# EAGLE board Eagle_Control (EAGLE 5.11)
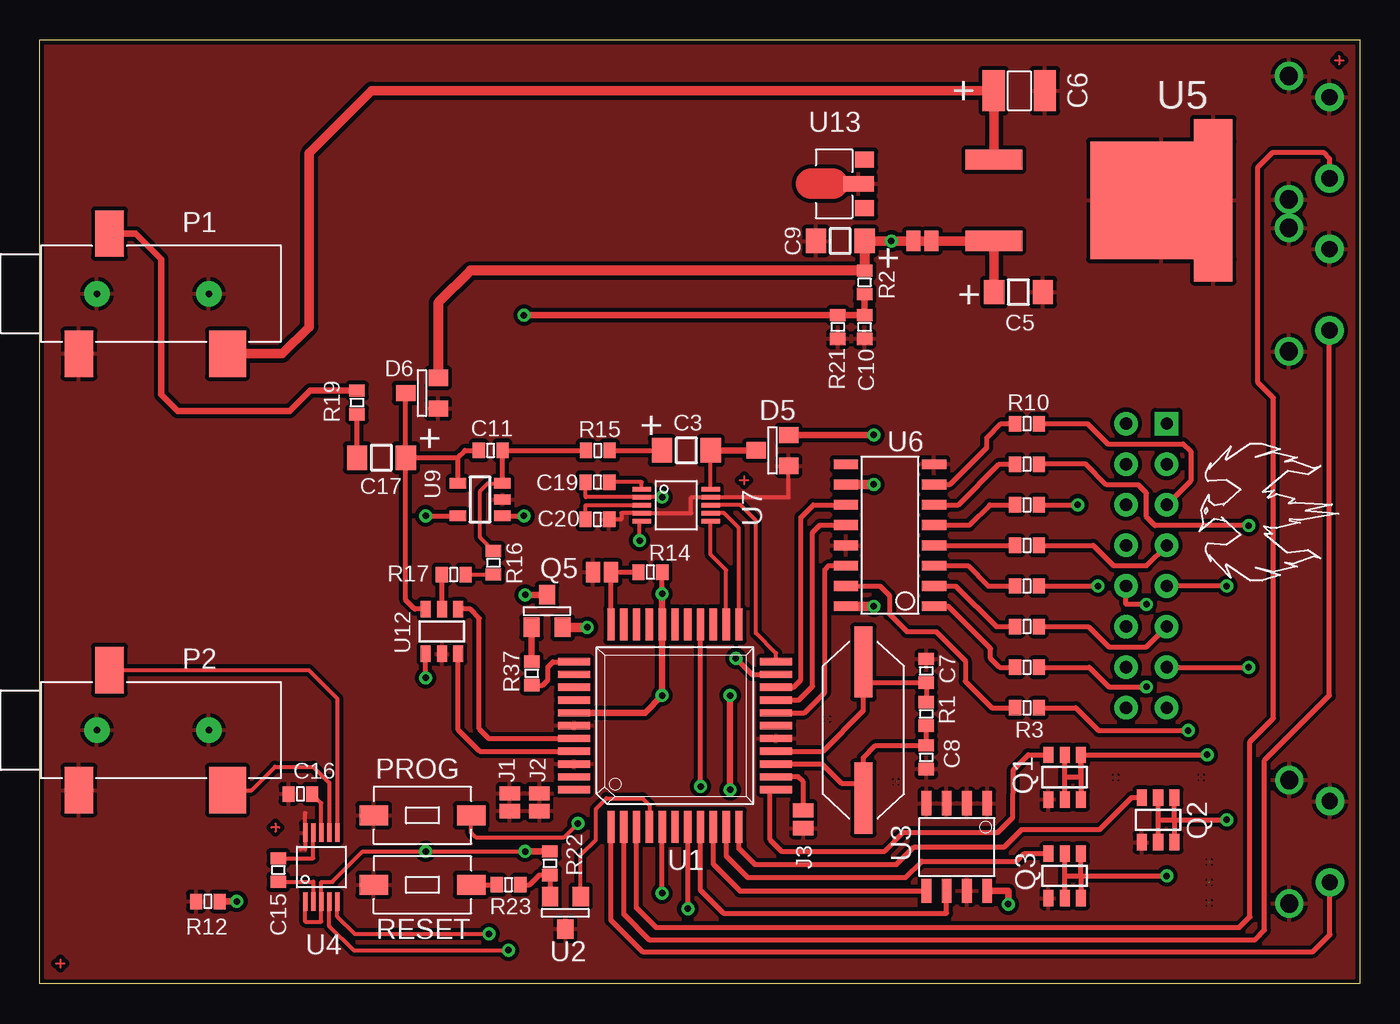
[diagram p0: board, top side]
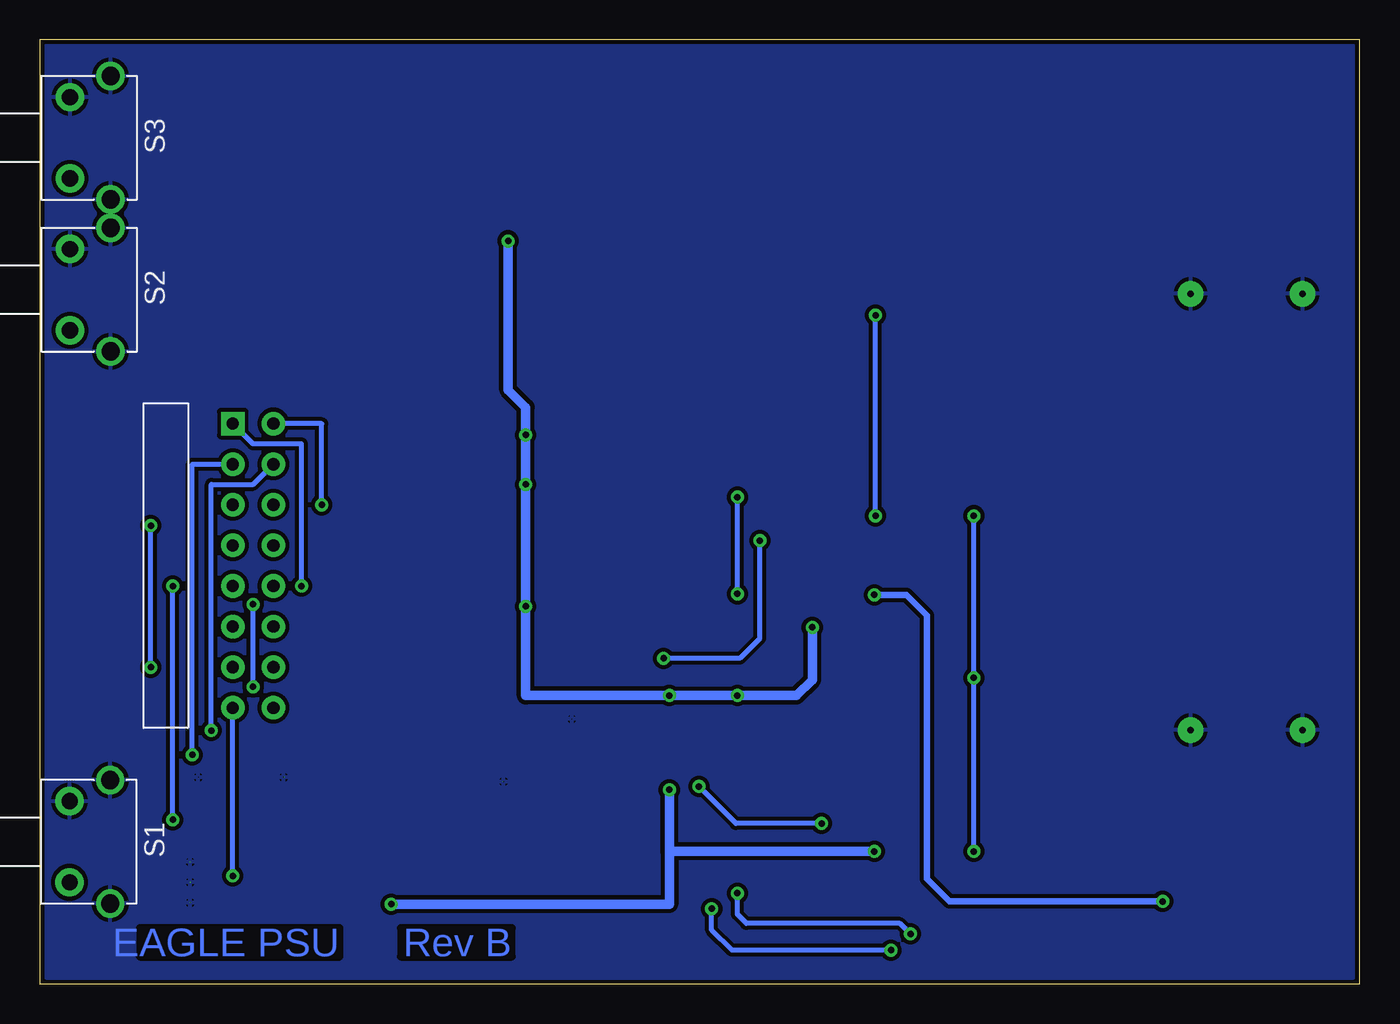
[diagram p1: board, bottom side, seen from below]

Size 82.55 x 59.05 mm. Coordinates in mm from the lower left corner, seen from the top.
Outline: 0,0 0,59.05 82.55,59.05 82.55,0 0,0
Copper layers (1*16): Top 0.035mm / dielectric 1.5mm / Bottom 0.035mm
Design rules "default *": minimum track width 10mil, minimum drill 1mil, track to track 8mil, track to pad 8mil, pad to pad 8mil, via to via 8mil, smd to smd 8mil, copper to edge 0mil, drill to drill 8mil, minimum pad ring 0mil, minimum via ring 0mil, stop-mask expansion 4mil, vias tented up to drill 20mil, thermal gap 10mil

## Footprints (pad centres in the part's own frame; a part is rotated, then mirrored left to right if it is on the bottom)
C1206 = smd 1.524 x 1.27: P$1 0,1.524; P$2 0,-1.524
1210 = smd 1.397 x 2.591: 1 -1.6,0; 2 1.6,0
C0603 = smd 0.762 x 0.965: P$1 -0.737,0; P$2 0.737,0
SOT23 = smd 1.016 x 1.219: 1 -0.94,1.016; 2 0.991,1.016; 3 0.025,-1.016
SMJUMP-S = smd 0.889 x 1.27: P$1 0.559,0; P$2 -0.559,0
DIP16_RA = drill 0.762 pad 1.473 square: P$1 -8.89,-1.27 | drill 0.762 pad 1.473 round: P$2 -6.35,-1.27; P$3 -3.81,-1.27; P$4 -1.27,-1.27; P$5 1.27,-1.27; P$6 3.81,-1.27; P$7 6.35,-1.27; P$8 8.89,-1.27; P$9 8.89,1.27; P$10 6.35,1.27; P$11 3.81,1.27; P$12 1.27,1.27; P$13 -1.27,1.27; P$14 -3.81,1.27; P$15 -6.35,1.27; P$16 -8.89,1.27
CSM7 = smd 4.445 x 1.143: P$1 0,0; P$2 8.509,0
GNDVIA = drill 0.025 pad 0.046 round: P$1 0,0
3.5MMST_RA_SMT-3 = smd 1.803 x 2.896: P$1 5.131,3.759; P$2 3.226,-3.759 | smd 2.311 x 2.896: P$3 -4.166,3.759 | drill 0.406 pad 1.587 round: P$5 -2.997,0; P$6 4.013,0
SPST3X6 = smd 1.778 x 1.27: P$1 3.048,0; P$2 -3.048,0
SOT6 = smd 1.016 x 0.635: P$1 1.397,-1.016; P$2 1.397,0; P$3 -1.397,0; P$4 -1.397,-1.016; P$5 -1.397,1.016; P$6 1.397,1.016
C603_90 = smd 0.965 x 0.762: P$1 0,0.737; P$2 0,-0.737
TACTRA = drill 1.143 pad 1.778 round: P$1 1.346,-3.861; P$2 1.346,3.861 | drill 1.016 pad 1.778 round: P$3 -1.194,2.54; P$4 -1.194,-2.54
QFP-44 = smd 0.457 x 2.007: 1 -4,-6.325; 2 -3.2,-6.325; 3 -2.4,-6.325; 4 -1.6,-6.325; 5 -0.8,-6.325; 6 0,-6.325; 7 0.8,-6.325; 8 1.6,-6.325; 9 2.4,-6.325; 10 3.2,-6.325; 11 4,-6.325; 23 4,6.325; 24 3.2,6.325; 25 2.4,6.325; 26 1.6,6.325; 27 0.8,6.325; 28 0,6.325; 29 -0.8,6.325; 30 -1.6,6.325; 31 -2.4,6.325; 32 -3.2,6.325; 33 -4,6.325 | smd 2.007 x 0.457: 12 6.325,-4; 13 6.325,-3.2; 14 6.325,-2.4; 15 6.325,-1.6; 16 6.325,-0.8; 17 6.325,0; 18 6.325,0.8; 19 6.325,1.6; 20 6.325,2.4; 21 6.325,3.2; 22 6.325,4; 34 -6.325,4; 35 -6.325,3.2; 36 -6.325,2.4; 37 -6.325,1.6; 38 -6.325,0.8; 39 -6.325,0; 40 -6.325,-0.8; 41 -6.325,-1.6; 42 -6.325,-2.4; 43 -6.325,-3.2; 44 -6.325,-4
SO-8 = smd 0.61 x 1.524: 1 -1.27,-2.743; 2 0,-2.743; 3 1.27,-2.743; 4 2.54,-2.743; 5 2.54,2.743; 6 1.27,2.743; 7 0,2.743; 8 -1.27,2.743
10UMAX = smd 0.279 x 1.143: P$1 -1,-2.16; P$2 -0.5,-2.16; P$3 0,-2.16; P$4 0.5,-2.16; P$5 1,-2.16; P$6 1,2.16; P$7 0.5,2.16; P$8 0,2.16; P$9 -0.5,2.16; P$10 -1,2.16
TO263 = smd 7.366 x 8.89: P$1 0,0 | smd 1.27 x 3.556: P$2 -2.54,-10.477; P$3 2.54,-10.477 | smd 10.16 x 2.413: P$4 0,3.239
SO-16 = smd 0.61 x 1.524: 1 -3.81,-2.819; 2 -2.54,-2.819; 3 -1.27,-2.819; 4 0,-2.819; 5 1.27,-2.819; 6 2.54,-2.819; 7 3.81,-2.819; 8 5.08,-2.819; 9 5.08,2.692; 10 3.81,2.692; 11 2.54,2.692; 12 1.27,2.692; 13 0,2.692; 14 -1.27,2.692; 15 -2.54,2.692; 16 -3.81,2.692
SOT23-5 = smd 1.016 x 0.635: 1 -1.397,1.016; 2 -1.397,0; 3 -1.397,-1.016; 4 1.397,-1.016; 5 1.397,1.016
SOT-89 = smd 0.991 x 1.194: 1 -1.524,-1.829; 2 1.524,-1.829 | smd 0.991 x 1.905: 3 0,-1.448

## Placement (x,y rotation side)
C3  [C1206]  40.44,33.38 90 top
C5  [C1206]  61.21,43.28 90 top
C6  [1210]  61.26,55.88 0 top
C7  [C0603]  55.45,19.58 90 top
C8  [C0603]  55.45,14.17 90 top
C9  [C1206]  50.06,46.48 90 top
C10  [C0603]  51.59,41.1 90 top
C11  [C0603]  28.19,33.38 0 top
C15  [C0603]  14.91,7.12 90 top
C16  [C0603]  16.29,11.87 0 top
C17  [C1206]  21.36,32.92 90 top
C19  [C0603]  34.87,31.39 0 top
C20  [C0603]  34.87,29.06 0 top
D5  [SOT23]  45.82,33.4 270 top
D6  [SOT23]  23.9,36.98 270 top
E$1  [SMJUMP-S]  29.39,11.37 90 top
E$2  [SMJUMP-S]  55.21,46.48 0 top
E$4  [SMJUMP-S]  31.24,11.37 90 top
E$11  [PHOENIX_LOGO]  75.69,29.51 90 top
E$12  [DIP16_RA]  69.22,26.16 270 bottom
E$13  [CSM7]  51.51,11.62 90 top
E$15  [SMJUMP-S]  35.17,25.76 180 top
E$16  [GNDVIA]  73.15,7.62 0 top
E$17  [GNDVIA]  73.15,6.35 0 top
E$18  [GNDVIA]  73.15,5.08 0 top
E$19  [GNDVIA]  67.31,12.93 0 top
E$20  [GNDVIA]  72.64,12.93 0 top
E$21  [GNDVIA]  49.28,16.56 0 top
E$22  [GNDVIA]  53.54,12.65 0 top
E$23  [SMJUMP-S]  47.75,10.3 90 top
P1  [3.5MMST_RA_SMT-3]  7.57,43.18 180 top
P2  [3.5MMST_RA_SMT-3]  7.57,15.88 180 top
PROG  [SPST3X6]  23.93,10.54 180 top
Q1  [SOT6]  64.11,12.93 270 top
Q2  [SOT6]  69.95,10.26 270 top
Q3  [SOT6]  64.11,6.76 270 top
Q5  [SOT23]  31.75,23.32 180 top
R1  [C0603]  55.45,16.89 90 top
R2  [C0603]  51.59,43.89 90 top
R3  [C603_90]  61.75,17.27 90 top
R4  [C603_90]  61.75,19.81 90 top
R5  [C603_90]  61.75,22.35 90 top
R6  [C603_90]  61.75,24.89 90 top
R7  [C603_90]  61.75,27.43 90 top
R8  [C603_90]  61.75,29.97 90 top
R9  [C603_90]  61.75,32.51 90 top
R10  [C603_90]  61.75,35.05 90 top
R12  [C0603]  10.5,5.16 0 top
R14  [C0603]  38.19,25.76 180 top
R15  [C0603]  34.9,33.38 0 top
R16  [C0603]  28.37,26.34 90 top
R17  [C0603]  25.88,25.6 0 top
R19  [C0603]  19.84,36.37 270 top
R21  [C0603]  49.91,41.1 90 top
R22  [C0603]  31.9,7.54 90 top
R23  [C0603]  29.31,6.2 0 top
R37  [C0603]  30.76,19.42 90 top
RESET  [SPST3X6]  23.93,6.2 180 top
S1  [TACTRA]  79.5,8.89 0 bottom
S2  [TACTRA]  79.48,43.43 0 bottom
S3  [TACTRA]  79.48,52.93 0 bottom
U1  [QFP-44]  39.73,16.15 0 top
U2  [SOT23]  32.84,4.45 0 top
U3  [SO-8]  57.99,8.56 180 top
U4  [10UMAX]  17.6,7.3 0 top
U5  [TO263]  70.15,49.02 270 top
U6  [SO-16]  53.11,27.43 90 top
U7  [10UMAX]  39.8,29.95 270 top
U9  [SOT23-5]  27.53,30.3 180 top
U12  [SOT6]  25.15,22.05 90 top
U13  [SOT-89]  49.76,50.05 90 top

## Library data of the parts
C3 C5 C7-C11 C15-C17 C19 C20 D5 D6 E$16-E$22 Q1-Q3 Q5 R1-R10 R12 R14-R17 R19 R21-R23 R37 U2 U9 U12 = RF
C6 U13 = SMD
E$1 E$2 E$4 E$11 E$13 E$15 E$23 P1 P2 PROG RESET S1-S3 = WJC
E$12 = pinhead
U1 U3-U7 = SMD-IC

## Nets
$BIAS: C10.P$2 R2.P$1 R21.P$2 U9.1
$GND: C5.P$2 C6.2 C7.P$2 C8.P$1 C9.P$1 C10.P$1 C16.P$1 C20.P$2 D5.2 D6.2 E$1.P$1 E$1.P$2 E$4.P$1 E$4.P$2 E$15.P$1 E$16.P$1 E$17.P$1 E$18.P$1 E$19.P$1 E$20.P$1 E$21.P$1 E$22.P$1 E$23.P$2 P1.P$1 P1.P$5 P1.P$6 P2.P$1 P2.P$5 P2.P$6 PROG.P$1 Q1.P$1 Q2.P$1 Q3.P$1 R12.P$1 R21.P$1 RESET.P$1 S1.P$1 S1.P$2 S1.P$3 S2.P$1 S2.P$2 S2.P$3 S3.P$1 S3.P$2 S3.P$3 U1.16 U1.39 U1.42 U2.3 U3.1 U3.2 U3.3 U3.4 U3.7 U4.P$10 U5.P$1 U5.P$4 U6.8 U6.13 U7.P$4 U7.P$9 U9.2 U12.P$3 U13.3
$VCC: C5.P$1 C9.P$2 C19.P$1 D5.1 D6.1 E$2.P$1 E$2.P$2 Q5.1 R2.P$2 R14.P$1 R22.P$2 U1.29 U1.38 U3.8 U4.P$1 U4.P$3 U5.P$3 U6.10 U6.16 U7.P$2 U9.5 U12.P$5
S$1: U1.4 U2.2
S$2: U1.5 U4.P$5
S$4: U1.8 U3.6
S$5: U1.7 U4.P$4
S$6: U1.9 U3.5
S$7: PROG.P$2 U1.26
S$8: R4.P$1 U6.1
S$9: Q3.P$4 U1.10
S$10: Q2.P$4 U1.11
S$11: R5.P$1 U6.2
S$12: R6.P$1 U6.3
S$13: R7.P$1 U6.4
S$14: R8.P$1 U6.5
S$15: R9.P$1 U6.6
S$16: R10.P$1 U6.7
S$17: R3.P$1 U6.15
S$18: E$12.P$15 R3.P$2
S$19: E$12.P$12 R4.P$2
S$20: E$12.P$6 R5.P$2
S$21: E$12.P$1 R6.P$2
S$22: E$12.P$4 R7.P$2
S$23: E$12.P$16 R8.P$2
S$24: E$12.P$7 R9.P$2
S$25: E$12.P$3 R10.P$2
S$26: E$12.P$2 Q1.P$2 Q1.P$3 Q1.P$5 Q1.P$6
S$27: Q1.P$4 U1.12
S$28: C6.1 P1.P$3 U5.P$2
S$29: C7.P$1 E$13.P$2 R1.P$2 U1.15
S$30: S1.P$4 U1.1
S$31: E$12.P$5 Q2.P$2 Q2.P$3 Q2.P$5 Q2.P$6
S$32: E$12.P$8 Q3.P$2 Q3.P$3 Q3.P$5 Q3.P$6
S$33: S2.P$4 U1.2
S$34: C8.P$2 E$13.P$1 R1.P$1 U1.14
S$35: S3.P$4 U1.3
S$36: U1.24 U7.P$6
S$37: U1.23 U7.P$7
S$38: U1.22 U7.P$8
S$39: U1.21 U7.P$5
S$40: R37.P$1 U1.34
S$41: U1.20 U6.11
S$42: U1.19 U6.12
S$43: U1.18 U6.14
S$44: Q5.3 R12.P$2
S$45: P1.P$2 R19.P$1
S$46: P2.P$3 U4.P$7
S$49: E$15.P$2 R14.P$2 U1.33
S$50: C15.P$2 U4.P$9
S$51: C15.P$1 U4.P$2
S$52: C3.P$1 R15.P$2
S$55: C3.P$2 D5.3 U7.P$10
S$56: P2.P$2 U4.P$6
S$57: C11.P$1 C17.P$2 D6.3 U9.4 U12.P$6
S$59: R17.P$1 U12.P$2
S$60: R22.P$1 R23.P$2 U2.1
S$61: C11.P$2 R15.P$1 R16.P$2 U9.3
S$65: R23.P$1 RESET.P$2
S$72: C16.P$2 U4.P$8
S$73: C17.P$1 R19.P$2
S$75: C19.P$2 U7.P$1
S$76: C20.P$1 U7.P$3
S$78: U1.40 U12.P$1
S$83: U1.41 U12.P$4
S$84: E$23.P$1 U1.13
S$85: R16.P$1 R17.P$2
S$93: Q5.2 R37.P$2

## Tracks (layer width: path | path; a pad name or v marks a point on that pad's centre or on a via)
$BIAS  (via drill 0.41 pad 0.81)
  Top 0.305: U9.1 v30.28,29.29
  Top 0.406: R2.P$1 C10.P$2 R21.P$2 v30.28,41.83
  Bottom 0.305: v30.28,29.29 v30.28,41.83
$GND
  Top 0.254: 16.31,8.43 16.6,8.43 U4.P$10 16.6,10.68 16.59,10.69 | D5.2 46.84,30.45 U7.P$9 40.74,30.45 40.74,29.45 U7.P$4 36.37,29.45 36.37,29.06 C20.P$2
  pour Top (isolate 0.254): 0.38,0.38 0.38,58.67 82.17,58.67 82.17,0.38
  pour Bottom (isolate 0.254): 0.38,0.38 0.38,58.67 82.17,58.67 82.17,0.38
$VCC  (via drill 0.41 pad 0.81)
  Top 0.254: C19.P$1 34.14,30.45 U7.P$2 v38.92,30.45 | U1.38 | v30.35,8.28 v24.13,8.28 20.19,8.28 18.29,6.38 17.6,6.38 U4.P$3 17.6,3.89 16.6,3.89 U4.P$1
  Top 0.305: v38.92,24.4 R14.P$1 | v24.13,29.29 U9.5 | v24.13,19.15 U12.P$5
  Top 0.406: v52.17,34.34 D5.1 | v38.92,24.4 U1.29 v38.92,18.03 37.85,16.95 U1.38 | U3.8 60.58,5.82 v60.58,4.98 | v43.18,12.14 v43.18,18.03 | v30.35,8.28 R22.P$2
  Top 0.61: C5.P$1 59.68,43.28 U5.P$3 E$2.P$1 E$2.P$2 v53.26,46.48 C9.P$2 | v52.17,31.24 U6.10 | v52.17,23.62 U6.16 | v34.24,22.3 Q5.1
  Top 0.635: D6.1 24.92,42.62 26.92,44.63 R2.P$2 C9.P$2
  Bottom 0.305: v38.92,24.4 v38.92,30.45 | v24.13,29.29 v24.13,19.15 v24.13,8.28
  Bottom 0.61: v53.26,46.48 53.26,37.16 52.17,36.07 v52.17,34.34 v52.17,31.24 v52.17,23.62 52.17,18.03 v43.18,18.03 v38.92,18.03 35.23,18.03 34.24,19.02 v34.24,22.3 | v60.58,4.98 43.18,4.98 43.18,8.28 | 43.18,8.28 v43.18,12.14 | v30.35,8.28 43.18,8.28
S$1
  Top 0.254: U1.4 38.12,11.18 37.69,11.61 35.43,11.61 34.77,10.95 34.77,9.02 33.83,8.08 U2.2
S$2  (via drill 0.41 pad 0.81)
  Top 0.254: v28.09,3.12 19.68,3.12 18.6,4.21 U4.P$5
  Top 0.305: v38.92,5.66 U1.5
  Bottom 0.305: v28.09,3.12 28.75,3.79 38.35,3.79 38.92,4.36 v38.92,5.66
S$4
  Top 0.305: U3.6 56.72,4.42 42.75,4.42 41.33,5.84 U1.8
S$5  (via drill 0.41 pad 0.81)
  Top 0.254: v29.31,2.11 19.61,2.11 18.1,3.62 U4.P$4
  Top 0.305: v40.53,4.7 U1.7
  Bottom 0.305: v40.53,4.7 40.53,3.37 39.27,2.11 v29.31,2.11
S$6
  Top 0.305: U3.5 43.79,5.82 42.13,7.48 U1.9
S$7  (via drill 0.41 pad 0.81)
  Top 0.254: PROG.P$2 26.98,9.45 27.25,9.17 32.79,9.17 v33.66,10.03
  Top 0.305: v41.33,12.34 U1.26
  Bottom 0.305: v33.66,10.03 39.01,10.03 v41.33,12.34
S$8
  Top 0.305: U6.1 56.82,23.62 59.46,20.98 59.46,20.37 60.02,19.81 R4.P$1
S$9
  Top 0.305: U1.10 42.93,8 44.27,6.66 54.15,6.66 55.17,7.67 61.11,7.67 61.59,8.15 Q3.P$4
S$10
  Top 0.305: Q2.P$4 68.3,11.66 66.29,9.65 61.42,9.65 60.33,8.56 54.69,8.56 53.59,7.47 44.73,7.47 43.73,8.47 U1.11
S$11
  Top 0.305: U6.2 57.28,24.89 59.82,22.35 R5.P$1
S$12
  Top 0.305: U6.3 58.04,26.16 59.31,24.89 R6.P$1
S$13
  Top 0.305: U6.4 R7.P$1
S$14
  Top 0.305: U6.5 58.14,28.7 59.41,29.97 R8.P$1
S$15
  Top 0.305: U6.6 57.45,29.97 59.99,32.51 R9.P$1
S$16
  Top 0.305: U6.7 56.92,31.24 59.23,33.55 59.23,34.16 60.12,35.05 R10.P$1
S$17
  Top 0.305: U6.15 52.55,24.89 53.14,24.31 53.14,23.14 54.23,22.05 56.06,22.05 57.89,20.22 57.89,18.92 59.54,17.27 R3.P$1
S$18  (via drill 0.41 pad 0.81)
  Top 0.305: R3.P$2 64.8,17.27 66.22,15.85 v71.83,15.85
  Bottom 0.305: v71.83,15.85 71.83,31.24 69.22,31.24 E$12.P$15
S$19  (via drill 0.41 pad 0.81)
  Top 0.305: E$12.P$12 67.94,23.75 v69.22,23.75 | R4.P$2 65.63,19.81 66.85,18.59 v69.22,18.59
  Bottom 0.305: v69.22,18.59 v69.22,23.75
S$20
  Top 0.305: R5.P$2 65.58,22.35 66.85,21.08 69.22,21.08 E$12.P$6
S$21  (via drill 0.41 pad 0.81)
  Top 0.305: R6.P$2 v66.19,24.89
  Bottom 0.305: v66.19,24.89 66.19,33.78 69.22,33.78 E$12.P$1
S$22
  Top 0.305: R7.P$2 65.89,27.43 67.16,26.16 69.22,26.16 E$12.P$4
S$23  (via drill 0.41 pad 0.81)
  Top 0.305: R8.P$2 v64.92,29.97
  Bottom 0.305: v64.92,29.97 64.92,35.05 E$12.P$16
S$24  (via drill 0.41 pad 0.81)
  Top 0.305: R9.P$2 65.43,32.51 66.73,31.22 68.71,31.22 69.22,30.71 69.22,29.21 69.75,28.68 v75.62,28.68 | E$12.P$7 v75.62,19.81
  Bottom 0.305: v75.62,19.81 v75.62,28.68
S$25
  Top 0.305: R10.P$2 65.53,35.05 66.8,33.78 71.53,33.78 71.98,33.33 71.98,31.47 E$12.P$3
S$26  (via drill 0.41 pad 0.81)
  Top 0.305: Q1.P$5 Q1.P$6 | Q1.P$3 Q1.P$2 64.11,12.95 65.13,12.95 Q1.P$5 | Q1.P$5 v73.03,14.33
  Bottom 0.305: E$12.P$2 73.03,32.51 v73.03,14.33
S$27
  Top 0.305: Q1.P$4 61.82,14.33 60.88,13.39 60.86,10.41 59.92,9.47 54.03,9.47 52.86,8.31 46.38,8.31 45.67,9.02 45.67,12.15 U1.12
S$28
  Top 0.61: U5.P$2 59.68,55.88 C6.1 20.75,55.88 16.84,51.97 16.84,41.1 15.16,39.42 P1.P$3
S$29
  Top 0.305: U1.15 48.97,14.55 51.51,17.09 51.51,18.85 | 51.51,18.85 E$13.P$2 51.51,20.62 | R1.P$2 C7.P$1 51.51,18.85
S$30
  Top 0.305: S1.P$4 80.7,3.07 79.63,2.01 37.69,2.01 35.71,3.99 35.71,9.82 U1.1
S$31  (via drill 0.41 pad 0.81)
  Top 0.305: 70.97,10.26 Q2.P$5 | 70.97,10.26 Q2.P$6 | Q2.P$3 Q2.P$2 69.95,10.26 70.97,10.26 | v74.24,24.89 E$12.P$5 | 70.97,10.26 v74.24,10.26
  Bottom 0.305: v74.24,10.26 v74.24,24.89
S$32  (via drill 0.41 pad 0.81)
  Top 0.305: 65.13,6.76 Q3.P$5 | 65.13,6.76 Q3.P$6 | Q3.P$3 Q3.P$2 64.11,6.76 65.13,6.76 | 65.13,6.76 v70.48,6.76
  Bottom 0.305: v70.48,6.76 E$12.P$8
S$33
  Top 0.305: S2.P$4 80.67,18.03 76.61,13.97 76.61,3.35 76.02,2.77 38.1,2.77 36.52,4.34 U1.2
S$34
  Top 0.305: R1.P$1 C8.P$2 52.27,14.91 51.51,14.15 51.51,12.39 | 51.51,12.39 E$13.P$1 | U1.14 48.93,13.75 50.14,12.55 51.36,12.55 51.51,12.39
S$35
  Top 0.305: S3.P$4 80.67,51.64 80.29,52.02 77.11,52.02 76.2,51.1 76.2,37.62 77.17,36.65 77.17,16.61 75.69,15.14 75.69,4.19 75.03,3.53 38.53,3.53 37.31,4.75 37.31,9.82 U1.3
S$36
  Top 0.254: U1.24 42.93,25.88 41.96,26.85 U7.P$6
S$37
  Top 0.254: U1.23 43.73,28.51 42.79,29.45 U7.P$7
S$38
  Top 0.254: U1.22 46.05,20.68 44.78,21.95 44.78,28.98 43.81,29.95 U7.P$8
S$39  (via drill 0.41 pad 0.81)
  Top 0.254: U7.P$5 37.52,28.95 37.52,28.8 v37.52,27.74
  Top 0.305: U1.21 44.55,19.36 v43.54,20.37
  Bottom 0.305: v43.54,20.37 38.76,20.37 37.52,21.61 v37.52,27.74
S$40
  Top 0.305: U1.34 32.09,20.16 31.77,19.84 31.77,19.02 31.43,18.68 R37.P$1
S$41
  Top 0.305: U1.20 47.13,18.55 47.6,19.02 47.6,29.18 48.39,29.97 U6.11
S$42
  Top 0.305: U1.19 47.47,17.75 48.34,18.62 48.34,28.25 48.79,28.7 U6.12
S$43
  Top 0.305: U6.14 49.35,26.16 49.1,25.91 49.1,18.24 47.82,16.95 U1.18
S$44  (via drill 0.41 pad 0.81)
  Top 0.406: 11.24,5.14 R12.P$2 v12.32,5.16 | v30.35,24.33 Q5.3
  Bottom 0.406: v12.32,5.16 25.65,5.16 27.08,6.58 27.08,23.06 28.35,24.33 v30.35,24.33
S$45
  Top 0.406: R19.P$1 16.89,37.11 15.62,35.84 8.61,35.84 7.59,36.85 7.59,45.34 5.99,46.94 P1.P$2
S$46
  Top 0.254: U4.P$7 18.1,12.58 17.09,13.59 14.71,13.59 13.23,12.12 P2.P$3
S$49
  Top 0.305: R14.P$2 E$15.P$2 U1.33
S$50
  Top 0.254: C15.P$2 17.1,7.86 U4.P$9
S$51
  Top 0.254: C15.P$1 17.1,6.39 U4.P$2
S$52
  Top 0.305: R15.P$2 C3.P$1
S$55
  Top 0.254: U7.P$10 C3.P$2
  Top 0.406: C3.P$2 D5.3
S$56
  Top 0.254: U4.P$6 18.6,17.85 16.82,19.63 P2.P$2
S$57
  Top 0.305: C17.P$2 26.14,32.92 | 26.14,32.92 26.59,33.38 C11.P$1 | 26.14,32.92 U9.4 | U12.P$6 23.44,23.44 22.89,24 C17.P$2 | C17.P$2 D6.3
S$59
  Top 0.305: U12.P$2 R17.P$1
S$60
  Top 0.305: U2.1 R22.P$1 31.24,6.81 30.63,6.2 R23.P$2
S$61
  Top 0.254: U9.3 28.02,31.32 27.53,30.84 27.53,27.91 R16.P$2
  Top 0.305: R15.P$1 C11.P$2 U9.3
S$63
  Top 0.127: 44.3,31.5 43.79,31.5
S$64
  Top 0.127: 44.04,31.75 44.04,31.24
S$65
  Top 0.305: RESET.P$2 R23.P$1
S$66
  Top 0.127: 14.99,9.78 14.48,9.78
S$67
  Top 0.127: 14.73,10.03 14.73,9.53
S$70
  Top 0.127: 1.52,1.27 1.02,1.27
S$71
  Top 0.127: 1.27,1.52 1.27,1.02
S$72
  Top 0.254: C16.P$2 17.6,11.3 U4.P$8
S$73
  Top 0.305: C17.P$1 R19.P$2
S$74
  Top 0.127: 81.03,57.78 81.53,57.78
S$75
  Top 0.254: C19.P$2 37.64,31.39 U7.P$1
S$76
  Top 0.254: C20.P$1 34.14,29.95 U7.P$3
S$77
  Top 0.127: 81.28,58.04 81.28,57.53
S$78
  Top 0.305: U1.40 28.08,15.35 27.48,15.95 27.48,22.89 26.92,23.44 U12.P$1
S$83
  Top 0.305: U1.41 27.51,14.55 26.16,15.9 U12.P$4
S$84
  Top 0.305: U1.13 47.42,12.95 47.75,12.62 E$23.P$1
S$85
  Top 0.254: R17.P$2 R16.P$1
S$93
  Top 0.406: R37.P$2 Q5.2

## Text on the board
Bottom: Rev B | EAGLE PSU
tPlace: + | + | + | + | + | J1 | J2 | J3
bStop: Rev B | EAGLE PSU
